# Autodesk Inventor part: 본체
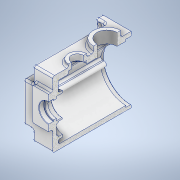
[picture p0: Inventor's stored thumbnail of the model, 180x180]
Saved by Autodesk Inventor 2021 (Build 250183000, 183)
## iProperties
Created: 2022-08
Part Number: 본체
Material: 알루미늄 6061
Document SubType Name: Modeling
Designer: Owner
Density: 2.7 g/cm^3
Appearance: 알루미늄 - 평지
Mass: 1404.34 g
Surface Area: 1171.2 cm^2
Volume: 520.127 cm^3
Author: Owner
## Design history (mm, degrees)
sketch "스케치1"
  geometry: L1 (-49, -55)-(49, -55); L2 (49, -55)-(49, 55); L3 (49, 55)-(-49, 55); L4 (-49, 55)-(-49, -55); L5 (-49, -55)-(49, 55); L6 (49, -55)-(-49, 55); 1 further point
  constraints: 12 end point, 2 midpoint, 2 parallel, 1 horizontal, 1 perpendicular
  dimensions: "d0" = 98 distance of L3.end L2.end; "d1" = 110 distance of L2.end L1.end
extrude "돌출1" new body sketch "스케치1" distance "d2" = 130; taper "d3" = 0 deg
sketch "스케치3"
  geometry: L1 (49, 55)-(-49, 55) reference; L2 (49, 55)-(33, 55); L3 (33, 55)-(33, 28); L4 (33, 28)-(49, 28); L5 (49, 28)-(49, 55); L6 (49, -55)-(49, 55) reference; L7 (49, -55)-(33, -55); L8 (33, -55)-(33, -38); L9 (33, -38)-(49, -38); L10 (49, -38)-(49, -55); 3 further points
  constraints: 16 end point, 4 parallel, 2 horizontal, 2 perpendicular
  dimensions: "d4" = 27 distance of L2.end L3.end; "d5" = 16 distance between parallel lines of L5 L3; "d6" = 16 distance of L8.end L9.end; "d7" = 17 distance between parallel lines of L7 L9
extrude "돌출2" cut sketch "스케치3" distance "d8" = 120; taper "d9" = 0 deg
sketch "스케치4"
  geometry: L1 (-27, -21)-(27, -21); L2 (27, -21)-(27, 33); L3 (27, 33)-(-27, 33); L4 (-27, 33)-(-27, -21); L5 (-27, -21)-(27, 33); L6 (27, -21)-(-27, 33); L7 (-33, -55)-(33, -55) reference; 3 further points
  constraints: 12 end point, 3 midpoint, 2 parallel, 1 horizontal, 1 perpendicular, 1 vertical alignment
  dimensions: "d10" = 54 distance of L3.end L2.end; "d11" = 54 distance of L2.end L1.end; "d12" = 61 distance from line of L7 point (0, 6)
extrude "돌출3" join sketch "스케치4" distance "d13" = 7; taper "d14" = 0 deg
sketch "스케치7"
  geometry: L1 (98, 0)-(0, 0) reference; C1 r 15 at (49, -89); 2 further points
  constraints: 1 centre point, 1 midpoint, 1 vertical alignment
  dimensions: "d15" = 30 diameter of C1; "d16" = 89 distance from line of C1.centre L1
extrude "돌출4" join sketch "스케치7" distance "d17" = 5; taper "d18" = 0 deg
sketch "스케치8"
  geometry: L1 (98, 0)-(0, 0) reference; C1 r 22.5 at (49, -40); 2 further points
  constraints: 1 centre point, 1 midpoint, 1 vertical alignment
  dimensions: "d19" = 45 diameter of C1; "d20" = 40 distance of point (49, 0) C1.centre
extrude "돌출5" join sketch "스케치8" distance "d21" = 10; taper "d22" = 0 deg
sketch "스케치9"
  geometry: L1 (49, -55)-(-49, -55) reference; L2 (-23, 45)-(23, 45); L3 (23, 45)-(23, 30.143); L4 (-23, 30.143)-(-23, 45); A1 r 42 centre (0, -5) between (-23, 30.143) and (23, 30.143); 2 further points
  constraints: 6 end point, 2 point on circle, 2 vertical alignment, 1 centre point, 1 horizontal, 1 midpoint, 1 parallel, 1 perpendicular
  dimensions: "d23" = 84 diameter of A1; "d24" = 50 distance from line of L1 A1.centre; "d25" = 46 distance of L2.start L2.end; "d26" = 50 distance from line of L2 A1.centre
extrude "돌출6" cut sketch "스케치9" distance "d27" = 121; taper "d28" = 0 deg
fillet "모깎기1" dims "d29" = 6
fillet "모깎기2" dims "d30" = 3
sketch "스케치10"
  geometry: L1 (-20, 45)-(20, 45) reference; L2 (-23, 33.249)-(-23, 42) reference; L3 (23, 42)-(23, 33.249) reference; L4 (-26, 33.249)-(-26, 42); L5 (-20, 48)-(20, 48); L6 (26, 42)-(26, 33.249); A1 r 3 centre (-20, 42) between (-20, 45) and (-23, 42) reference; A2 r 6 centre (-29, 33.249) between (-25.375, 28.468) and (-23, 33.249) reference; A3 r 42 centre (0, -5) between (-25.375, 28.468) and (25.375, 28.468) reference; A4 r 6 centre (29, 33.249) between (23, 33.249) and (25.375, 28.468) reference; A5 r 3 centre (20, 42) between (23, 42) and (20, 45) reference; A6 r 3 centre (29, 33.249) between (26, 33.249) and (27.188, 30.859); A7 r 45 centre (0, -5) between (-27.187, 30.859) and (27.188, 30.859); A8 r 3 centre (-29, 33.249) between (-27.187, 30.859) and (-26, 33.249); A9 r 6 centre (-20, 42) between (-20, 48) and (-26, 42); A10 r 6 centre (20, 42) between (26, 42) and (20, 48); 1 further point
  constraints: 10 point on circle, 6 end point, 5 centre point, 7 other
  dimensions: "d31" = 3 distance between parallel lines of L3 L6
extrude "돌출7" cut sketch "스케치10" distance "d32" = 9; taper "d33" = 0 deg
sketch "스케치11"
  geometry: L1 (49, -55)-(-49, -55) reference; A1 r 21 centre (0, 6) between (8.978, -12.984) and (-8.978, -12.984); A2 r 15 centre (0, -25) between (-8.978, -12.984) and (8.978, -12.984); 1 further point
  constraints: 4 point on circle, 2 centre point, 2 vertical alignment
  dimensions: "d34" = 42 diameter of A1; "d36" = 30 diameter of A2; "d105" = 61 distance from line of L1 A1.centre; "d106" = 31 distance of A2.centre A1.centre
extrude "돌출8" join sketch "스케치11" distance "d38" = 7; taper "d39" = 0 deg
fillet "모깎기3" dims "d40" = 3
sketch "스케치12"
  geometry: A1 r 21 centre (0, 6) between (12.163, -11.119) and (-12.163, -11.119) reference; 2 further points
  constraints: 1 coincident
hole "구멍1" sketch "스케치12" at (0, 6) diameter "d42" = 28; stored, may be unused: countersink angle "d46" = 90 deg, drill point angle "d48" = 118 deg; dims "d43" = 8, "d44" = 35, "d45" = 10, "d47" = 10
sketch "스케치13"
  geometry: A1 r 15 centre (0, -25) between (-11.584, -15.47) and (11.584, -15.47) reference; 2 further points
  constraints: 1 coincident
hole "구멍2" sketch "스케치13" at (0, -25) diameter "d49" = 19; stored, may be unused: countersink angle "d53" = 90 deg, drill point angle "d55" = 0 deg; dims "d50" = 8, "d51" = 22, "d52" = 7, "d54" = 10
fillet "모깎기5" dims "d56" = 3
sketch "스케치14"
  geometry: L1 (49, -55)-(-49, -55) reference; L2 (36, -1)-(41.809, -1); L3 (36, -9)-(41.809, -9); A1 r 42 centre (0, -5) between (-25.375, 28.468) and (25.375, 28.468) reference; A2 r 4 centre (36, -5) between (36, -1) and (36, -9); 1 further point
  constraints: 4 end point, 4 point on circle, 2 horizontal, 2 tangent, 1 centre point
  dimensions: "d57" = 8 diameter of A2; "d58" = 50 distance from line of L1 A2.centre; "d59" = 36 horizontal distance of A2.centre point (0, 0)
extrude "돌출9" join sketch "스케치14" stored distance "d60" = 7; taper "d61" = 0 deg
fillet "모깎기6" dims "d62" = 3
sketch "스케치15"
  geometry: A1 r 4 centre (36, -5) between (36, -1) and (36, -9) reference; 2 further points
  constraints: 1 coincident
hole "구멍3" sketch "스케치15" at (36, -5) diameter "d63" = 3.242; stored, may be unused: countersink angle "d67" = 90 deg, drill point angle "d69" = 118 deg; dims "d64" = 7, "d65" = 22, "d66" = 7, "d68" = 9
fillet "모깎기7" dims "d70" = 3
fillet "모깎기8" dims "d71" = 3
sketch "스케치16"
  geometry: C1 r 14 at (0, 6) reference; C2 r 16 at (0, 6); 1 further point
  constraints: 1 centre point, 1 coincident
  dimensions: "d72" = 32 diameter of C2
extrude "돌출10" cut sketch "스케치16" distance "d73" = 8.3; taper "d74" = 0 deg
chamfer "모따기1" distance "d75" = 0.8; stored, may be unused: second distance "d76" = 2, angle "d77" = 30 deg
fillet "모깎기9" dims "d78" = 0.3
sketch "스케치17"
  geometry: C1 r 22.5 at (0, 0) reference; 2 further points
  constraints: 1 coincident
hole "구멍4" sketch "스케치17" at (0, 0) diameter "d79" = 33.376; stored, may be unused: countersink angle "d83" = 90 deg, drill point angle "d85" = 118 deg; dims "d80" = 70, "d81" = 22, "d82" = 7, "d84" = 9
sketch "스케치18"
  geometry: L1 (40, -9)-(0, -9) reference; 2 further points
  constraints: 1 vertical alignment
  dimensions: "d86" = 89 distance from line of point (20, 80) L1
hole "구멍5" sketch "스케치18" at (20, 80) diameter "d87" = 20; stored, may be unused: countersink angle "d91" = 90 deg, drill point angle "d93" = 118 deg; dims "d88" = 70, "d89" = 30, "d90" = 5, "d92" = 9
chamfer "모따기2" distance "d94" = 1; stored, may be unused: second distance "d95" = 2, angle "d96" = 30 deg
sketch "스케치19"
  geometry: L1 (-49, 55)-(49, 55) reference; C1 r 3.5 at (-42, 48); 1 further point
  constraints: 1 centre point
  dimensions: "d97" = 7 diameter of C1; "d98" = 42 horizontal distance of point (0, 0) C1.centre; "d99" = 7 distance from line of C1.centre L1
extrude "돌출11" cut sketch "스케치19" extent not by distance; stored distance "d100" = 0; taper "d101" = 0 deg
fillet "모깎기10" dims "d102" = 3
fillet "모깎기11" dims "d103" = 3
fillet "모깎기12" dims "d104" = 3
fillet "모깎기13" dims "d107" = 3
fillet "모깎기14" dims "d108" = 3
fillet "모깎기15" dims "d109" = 3
chamfer "모따기3" distance "d110" = 1; stored, may be unused: second distance "d111" = 2, angle "d112" = 30 deg
sketch "스케치20"
  geometry: L1 (-13, 80)-(-127, 80) reference; L2 (-130, 104)-(-130, 83) reference; 2 further points
  constraints: 1 other
  dimensions: "d113" = 33 distance from line of point (-65, 47) L1; "d114" = 65 distance from line of point (-65, 47) L2
feature "엠보싱1" sketch "스케치20" dims "d115" = 0.5, "d116" = 0
fillet "모깎기16" dims "d117" = 0.3
node "솔리드1"
mirror "미러1"
mirror "미러2"
mirror "미러3"
mirror "미러4"
feature "A9D066F2-1C7D-4E18-AEED-F7BC21143FA4" dims "d42" = 28, "d43" = 8, "d44" = 35, "d45" = 10, "d46" = 90 deg, "d47" = 10, "d48" = 118 deg
